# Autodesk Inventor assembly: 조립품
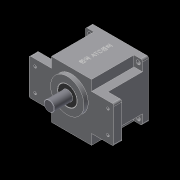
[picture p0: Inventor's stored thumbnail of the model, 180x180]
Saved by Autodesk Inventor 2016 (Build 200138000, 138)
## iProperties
Created: 2020-08
Part Number: 조립품
Material: 일반
Document SubType Name: Assembly
Designer: User
Author: User
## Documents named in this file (10)
- C:\Users\User\Desktop\700815V1004\조립품.iam
- C:\Users\User\Desktop\700815V1004\메인 축.ipt
- C:\Users\User\Desktop\700815V1004\베어링 608.ipt
- C:\Users\User\Desktop\700815V1004\베어링 6003.ipt
- C:\Users\User\Desktop\700815V1004\본체.ipt
- C:\Users\User\Desktop\700815V1004\볼트 M4.ipt
- C:\Users\User\Desktop\700815V1004\서브 축.ipt
- C:\Users\User\Desktop\700815V1004\오일 실 8 22 7.ipt
- C:\Users\User\Desktop\700815V1004\오일 실 17 32 8.ipt
- C:\Users\User\Desktop\700815V1004\커버.ipt
